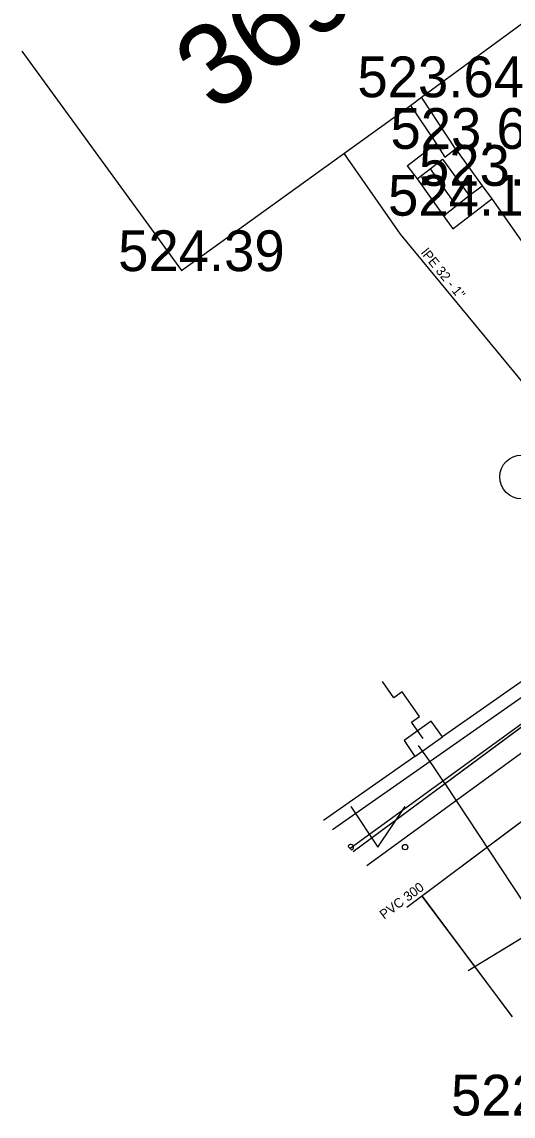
# Model space of a CAD drawing. Extents: x -668867 to -667827, y -1131943 to -1131019.
# Drawn here: x -668669.34 to -668660.29, y -1131521.01 to -1131500.87 of the extents above; entities that cross this region are included whole.
import ezdxf

# ---------------------------------------------------------------- set-up
doc = ezdxf.new("R2010")
doc.units = 0
for name, color, linetype in [('G_Bod_tecka', 7, 'Continuous'), ('G_Bod_vyska', 7, 'Continuous'), ('G_Budovy_Objekty', 7, 'Continuous'), ('G_Budovy_vstupy', 7, 'Continuous'), ('G_Cesty_Schody', 7, 'Continuous'), ('G_Cisla_popisna', 7, 'Continuous'), ('G_Plochy_zpevnene', 7, 'Continuous'), ('G_Ploty', 7, 'Continuous'), ('G_Site-Rozvadece', 7, 'Continuous'), ('G_Z_ELsilove_podz_kotovane', 7, 'Continuous'), ('G_Z_KANAL_podz_kotovane', 7, 'Continuous'), ('G_Z_PLYNY_podz_geodeticky', 7, 'Continuous'), ('G_Z_SPOJE_podz_geodeticky', 7, 'Continuous'), ('G_Z_SPOJE_podz_kotovane', 7, 'Continuous'), ('G_Z_SPOJE_podz_priblizne', 7, 'Continuous'), ('G_Z_VODA_podz_kotovane', 7, 'Continuous'), ('G_Zelen-Znacky', 7, 'Continuous'), ('Vrstva 12', 7, 'Continuous'), ('Vrstva 17', 7, 'Continuous'), ('Vrstva 26', 7, 'Continuous'), ('Vrstva 27', 7, 'Continuous'), ('Vrstva 3', 7, 'Continuous'), ('Vrstva 4', 7, 'Continuous')]:
    doc.layers.add(name, color=color, linetype=linetype)

msp = doc.modelspace()

# ---------------------------------------------------------------- linework, layer by layer
at = {"layer": 'G_Bod_tecka'}
for p, q in [((-668661.98, -1131502.26), (-668661.98, -1131502.26)), ((-668661.35, -1131503.21), (-668661.35, -1131503.21)), ((-668660.86, -1131503.89), (-668660.86, -1131503.89)), ((-668661.57, -1131504.44), (-668661.57, -1131504.44)), ((-668666.4, -1131505.46), (-668666.4, -1131505.46))]:
    msp.add_line(p, q, dxfattribs=at)
at = {"layer": 'G_Budovy_Objekty'}
for p, q in [((-668669.34, -1131501.41), (-668666.4, -1131505.45)), ((-668662.18, -1131502.41), (-668661.98, -1131502.26)), ((-668666.4, -1131505.45), (-668662.18, -1131502.41))]:
    msp.add_line(p, q, dxfattribs=at)
at = {"layer": 'G_Budovy_vstupy'}
msp.add_line((-668661.98, -1131502.26), (-668660, -1131500.81), dxfattribs=at)
at = {"layer": 'G_Cesty_Schody'}
for p, q in [((-668662.24, -1131503.52), (-668661.71, -1131503.11)), ((-668661.55, -1131503.36), (-668661.35, -1131503.21)), ((-668661.35, -1131503.21), (-668660.86, -1131503.89)), ((-668661.82, -1131503.58), (-668661.59, -1131503.4)), ((-668661.59, -1131503.4), (-668661.1, -1131504.07)), ((-668662.24, -1131503.52), (-668662.06, -1131503.76)), ((-668662.06, -1131503.76), (-668661.82, -1131503.58)), ((-668661.82, -1131503.58), (-668661.34, -1131504.26)), ((-668662.06, -1131503.76), (-668661.57, -1131504.44)), ((-668661.34, -1131504.26), (-668661.1, -1131504.07)), ((-668661.1, -1131504.07), (-668660.86, -1131503.89)), ((-668660.86, -1131503.89), (-668660.68, -1131504.13)), ((-668661.57, -1131504.44), (-668661.34, -1131504.26)), ((-668661.4, -1131504.68), (-668660.68, -1131504.13)), ((-668661.57, -1131504.44), (-668661.4, -1131504.68))]:
    msp.add_line(p, q, dxfattribs=at)
at = {"layer": 'G_Plochy_zpevnene'}
for p, q in [((-668661.35, -1131503.21), (-668661.98, -1131502.26)), ((-668662.18, -1131502.41), (-668661.71, -1131503.11)), ((-668661.71, -1131503.11), (-668661.55, -1131503.36))]:
    msp.add_line(p, q, dxfattribs=at)
for points in [[(-668660.68, -1131504.13), (-668656.32, -1131510.34), (-668656.18, -1131510.54)], [(-668662.986, -1131516.401), (-668655.74, -1131511.12)]]:
    msp.add_lwpolyline(points, dxfattribs=at)
at = {"layer": 'G_Ploty'}
for p, q in [((-668656.32, -1131510.34), (-668661.59, -1131514.03)), ((-668656.18, -1131510.54), (-668663.62, -1131515.742)), ((-668662.1, -1131514.39), (-668663.786, -1131515.57))]:
    msp.add_line(p, q, dxfattribs=at)
at = {"layer": 'G_Site-Rozvadece'}
msp.add_lwpolyline([(-668661.95, -1131514.06), (-668662.163, -1131513.76), (-668662.014, -1131513.654), (-668662.335, -1131513.205), (-668662.485, -1131513.31), (-668662.699, -1131513.011)], dxfattribs=at)
msp.add_lwpolyline([(-668662.3, -1131514.1), (-668662.1, -1131514.39), (-668661.59, -1131514.03), (-668661.8, -1131513.74)], close=True, dxfattribs=at)
at = {"layer": 'G_Z_ELsilove_podz_kotovane'}
msp.add_lwpolyline([(-668663.235, -1131516.142), (-668658.05, -1131512.3), (-668651.53, -1131507.82), (-668636.54, -1131497.04), (-668629.83, -1131492.22), (-668629.73, -1131491.85), (-668629.57, -1131492.08), (-668621.5, -1131486.25), (-668606.96, -1131475.86), (-668606.86, -1131475.52), (-668606.76, -1131475.72), (-668596.23, -1131468.15)], dxfattribs=at)
at = {"layer": 'G_Z_KANAL_podz_kotovane'}
for points in [[(-668640.74, -1131501.1), (-668662.245, -1131517.171)], [(-668661.97, -1131516.96), (-668660.307, -1131519.185)]]:
    msp.add_lwpolyline(points, dxfattribs=at)
at = {"layer": 'G_Z_PLYNY_podz_geodeticky'}
for points in [[(-668661.55, -1131514.89), (-668661.77, -1131514.56), (-668662.03, -1131514.19)], [(-668661.55, -1131514.89), (-668659.27, -1131518.34)]]:
    msp.add_lwpolyline(points, dxfattribs=at)
at = {"layer": 'G_Z_SPOJE_podz_geodeticky'}
msp.add_lwpolyline([(-668659.76, -1131499.32), (-668656.78, -1131497.22), (-668654.75, -1131500.39), (-668650.81, -1131506.44), (-668650.86, -1131507.14), (-668653.05, -1131508.79), (-668656.45, -1131511.14), (-668656.9, -1131511.45), (-668657.68, -1131511.93), (-668658.58, -1131512.67), (-668663.292, -1131516.083)], dxfattribs=at)
at = {"layer": 'G_Z_SPOJE_podz_kotovane'}
msp.add_lwpolyline([(-668659.76, -1131499.32), (-668656.78, -1131497.22), (-668654.75, -1131500.39), (-668650.81, -1131506.44), (-668650.86, -1131507.14), (-668653.05, -1131508.79), (-668656.45, -1131511.14), (-668656.9, -1131511.45), (-668657.68, -1131511.93), (-668658.58, -1131512.67), (-668663.292, -1131516.083)], dxfattribs=at)
at = {"layer": 'G_Z_SPOJE_podz_priblizne'}
msp.add_lwpolyline([(-668659.76, -1131499.32), (-668656.78, -1131497.22), (-668654.75, -1131500.39), (-668650.81, -1131506.44), (-668650.86, -1131507.14), (-668653.05, -1131508.79), (-668656.45, -1131511.14), (-668656.9, -1131511.45), (-668657.68, -1131511.93), (-668658.58, -1131512.67), (-668663.292, -1131516.083)], dxfattribs=at)
at = {"layer": 'G_Z_VODA_podz_kotovane'}
for points in [[(-668559.06, -1131445.68), (-668574.11, -1131456.23), (-668577.03, -1131458.24), (-668577.08, -1131458.28), (-668590.65, -1131468.18), (-668601, -1131474.8), (-668610.7, -1131482.06), (-668610.75, -1131482.09), (-668617.27, -1131486.68), (-668627.28, -1131493.39), (-668634.91, -1131499.35), (-668635.56, -1131499.77), (-668635.57, -1131499.77), (-668638, -1131501.36), (-668650.61, -1131511.17), (-668655.02, -1131514.63), (-668655.13, -1131514.7), (-668661.121, -1131518.339)], [(-668663.41, -1131503.29), (-668663.35, -1131503.38), (-668662.37, -1131504.78), (-668658.43, -1131509.55), (-668656.69, -1131511.58), (-668656.6, -1131511.78), (-668656.5, -1131511.98), (-668655.13, -1131514.7)]]:
    msp.add_lwpolyline(points, dxfattribs=at)
at = {"layer": 'G_Zelen-Znacky'}
for p, q in [((-668663.28, -1131515.31), (-668662.78, -1131516.06)), ((-668662.78, -1131516.06), (-668662.28, -1131515.31)), ((-668663.328, -1131516.046), (-668663.268, -1131516.108))]:
    msp.add_line(p, q, dxfattribs=at)
for centre, radius in [((-668660.132, -1131509.247), 0.403), ((-668662.28, -1131516.06), 0.05)]:
    msp.add_circle(centre, radius, dxfattribs=at)
msp.add_arc((-668663.28, -1131516.06), 0.05, 284.1539, 163.6438, dxfattribs=at)
at = {"layer": 'Vrstva 12'}
for points in [[(-668640.738, -1131501.103), (-668662.246, -1131517.17)], [(-668661.968, -1131516.963), (-668660.312, -1131519.18)]]:
    msp.add_lwpolyline(points, dxfattribs=at)
at = {"layer": 'Vrstva 17'}
msp.add_line((-668663.235, -1131516.142), (-668658.05, -1131512.3), dxfattribs=at)
at = {"layer": 'Vrstva 26'}
msp.add_lwpolyline([(-668663.411, -1131503.293), (-668663.35, -1131503.38), (-668662.37, -1131504.78), (-668658.43, -1131509.55), (-668656.69, -1131511.58), (-668656.6, -1131511.78), (-668656.498, -1131511.983), (-668655.134, -1131514.697)], dxfattribs=at)
at = {"layer": 'Vrstva 27'}
msp.add_lwpolyline([(-668559.059, -1131445.682), (-668574.109, -1131456.225), (-668577.025, -1131458.241), (-668577.075, -1131458.277), (-668590.645, -1131468.176), (-668601, -1131474.798), (-668610.7, -1131482.06), (-668610.75, -1131482.09), (-668617.268, -1131486.684), (-668627.279, -1131493.392), (-668634.906, -1131499.353), (-668635.564, -1131499.768), (-668635.565, -1131499.769), (-668638.004, -1131501.364), (-668650.614, -1131511.168), (-668655.025, -1131514.63), (-668655.134, -1131514.697), (-668661.121, -1131518.339)], dxfattribs=at)

# ---------------------------------------------------------------- texts
at = {"layer": 'G_Bod_vyska'}
for s, p in [('523.64', (-668663.158, -1131502.26)), ('523.60', (-668662.549, -1131503.21)), ('523.57', (-668662.024, -1131503.89)), ('524.19', (-668662.594, -1131504.44)), ('524.39', (-668667.566, -1131505.46)), ('522.83', (-668661.434, -1131521))]:
    msp.add_text(s, height=0.75, dxfattribs=at).set_placement(p)
at = {"layer": 'G_Cisla_popisna'}
msp.add_text('3698', height=1.5, rotation=36.0151, dxfattribs=at).set_placement((-668665.786, -1131502.571))
at = {"layer": 'Vrstva 3'}
msp.add_text('PVC 300', height=0.1755, rotation=36.7611, dxfattribs=at).set_placement((-668662.667, -1131517.397))
at = {"layer": 'Vrstva 4'}
msp.add_text('lPE 32 - 1"', height=0.17551, rotation=309.3357, dxfattribs=at).set_placement((-668661.999, -1131505.128))

doc.saveas('drawing.dxf')
